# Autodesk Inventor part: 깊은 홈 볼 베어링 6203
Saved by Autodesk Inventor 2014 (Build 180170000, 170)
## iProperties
Created: 2026-05
Part Number: 깊은 홈 볼 베어링 6203
Material: 일반
Document SubType Name: Modeling
Designer: dg
Density: 1 g/cm^3
Appearance: 기본값
Author: dg
Author: jhkim
Description: 깊은 그루브 볼 베어링
Creation Date: 2026-04-27
Sending System: Autodesk Inventor 2027
Preprocessor: ST-DEVELOPER v20.1
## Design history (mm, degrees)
node "깊은 홈 볼 베어링 62031"
body "Solid1"
node "Solid1_1"
node "Solid1_2"
node "Solid1_3"
node "Solid1_4"
node "Solid1_5"
node "Solid1_6"
node "Solid1_7"
node "Solid1_8"
node "기준1"
node "기준2"
node "기준3"
node "기준4"
node "기준5"
node "기준6"
node "기준7"
node "기준8"
node "기준9"
